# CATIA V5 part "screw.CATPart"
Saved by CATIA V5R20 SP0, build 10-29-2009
Part number: Part2
Bounding box of the stored display mesh (mm): x 0 to 35, y -5.5 to 5.5, z -5.5 to 5.5
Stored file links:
  D:\Catia Project\screw.CATPart
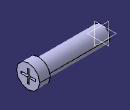
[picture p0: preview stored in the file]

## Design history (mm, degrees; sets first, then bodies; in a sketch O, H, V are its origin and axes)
Body1 (main body)
  Sketch1 on yz-plane, origin (0, 0, 0), H (0, 1, 0), V (0, 0, 1)
    circle A1 centre (0, 0) radius 4
    radius A1 = 4
  Pad1: profile Sketch1, direction (1, 0, 0), length 30
  Sketch2 on end face of Pad1, origin (30, 0, 0), H (0, 1, 0), V (0, 0, 1)
    circle A1 centre (0, 0) radius 5.5
    radius A1 = 5.5
  Pad2: profile Sketch2, direction (1, 0, 0), length 5
  Sketch3 on end face of Pad2, origin (35, 0, 0), H (0, 1, 0), V (0, 0, 1)
    line L1 (-3.5, 0.5) -> (-0.5, 0.5)
    point P2 (3.5, 0.5)
    line L2 (-3.5, -0.5) -> (-0.5, -0.5)
    point P3 (-3.5, -0.5)
    line L3 (-0.5, 3.1315) -> (-0.5, 0.5)
    line L4 (0.5, 3.1315) -> (0.5, 0.5)
    reference intersected line E1 through (0, 0) direction (0, 1) from zx-plane
    line L5 (-0.5, 3.1315) -> (0.5, 3.1315)
    line L6 (3.5, 0.5) -> (3.5, -0.5)
    line L7 (-3.5, 0.5) -> (-3.5, -0.5)
    line L8 (-0.5, -3.1435) -> (0.5, -3.1435)
    line L9 (-0.5, -0.5) -> (-0.5, -3.1435)
    line L10 (0.5, 0.5) -> (3.5, 0.5)
    line L11 (0.5, -0.5) -> (0.5, -3.1435)
    point P12 (0.5, -0.5)
    line L12 (0.5, -0.5) -> (3.5, -0.5)
    distance P3 L1 = 1
    distance H L2 = 0.5
    distance V P2 = 3.5
    distance E1 P3 = 3.5
    distance V L3 = 0.5
    distance V L4 = 0.5
    horizontal: L1 H, L2 H, L5 H, L8 H, L10 H, L12 H
    vertical: L3 V, L4 V, L6 V, L7 V, L9 V, L11 V
    coincidence: L3 L9, L1 L10, L2 P12, L4 L11, L2 L12
  Pocket1: profile Sketch3, direction (-1, 0, 0), length 3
